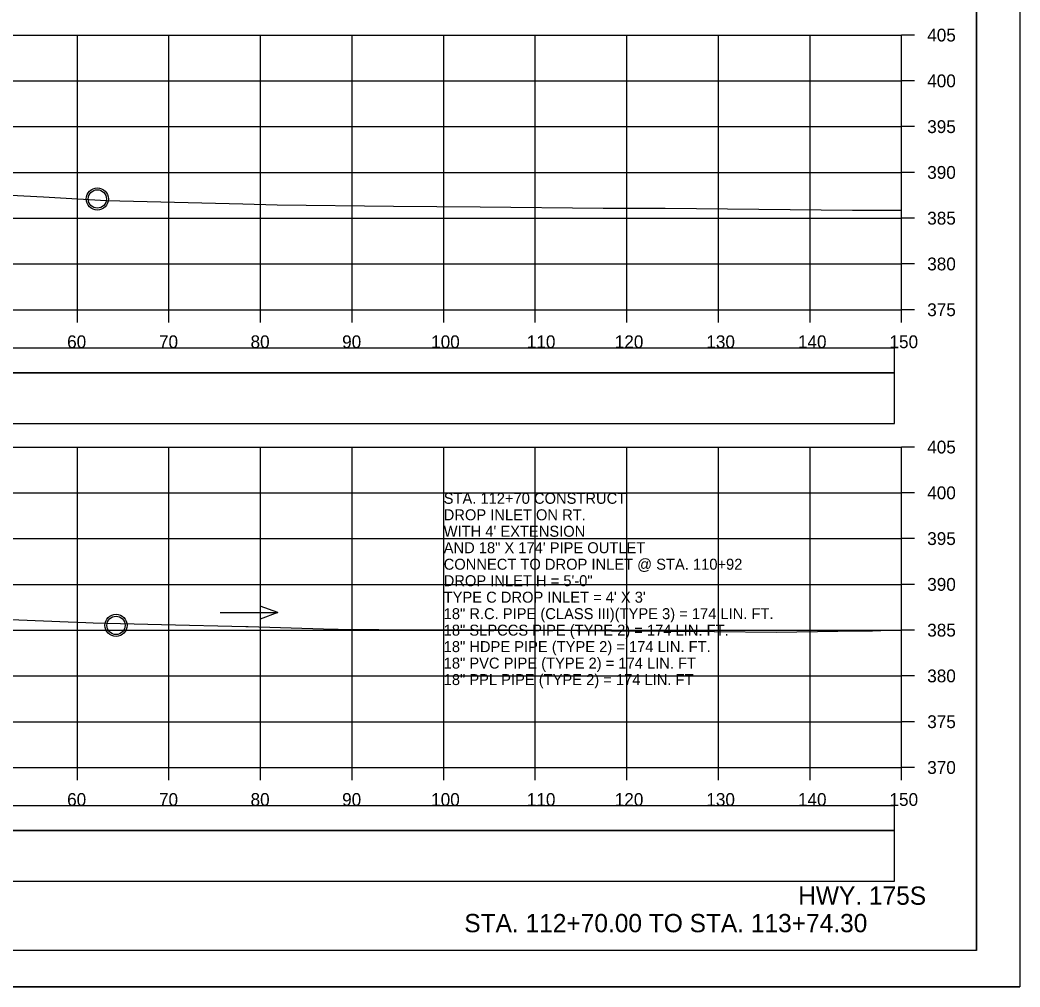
# Model space of a CAD drawing. Extents: x -37291014 to -37290680, y -936053 to -933067.
# Drawn here: x -37290789.4 to -37290680.2, y -933493.3 to -933387.6 of the extents above; entities that cross this region are included whole.
import ezdxf

# ---------------------------------------------------------------- set-up
doc = ezdxf.new("R2010")
doc.units = 0
for name, color, linetype in [('Default', 7, 'Continuous'), ('R_Axis', 7, 'Continuous'), ('R_Axis Annot', 7, 'Continuous'), ('R_Border', 7, 'Continuous'), ('R_Draft', 7, 'Continuous'), ('R_Exist Surface', 7, 'Continuous'), ('R_Grid', 7, 'Continuous'), ('R_No Plot', 7, 'Continuous'), ('R_Water', 7, 'Continuous'), ('R_Water Annot', 7, 'Continuous')]:
    doc.layers.add(name, color=color, linetype=linetype)

msp = doc.modelspace()

# ---------------------------------------------------------------- linework, layer by layer
at = {"layer": 'Default'}
for points in [[(-37290992.31, -933426.17), (-37290693.89, -933426.17), (-37290693.89, -933423.47), (-37290992.31, -933423.47)], [(-37290992.31, -933431.7), (-37290693.89, -933431.7), (-37290693.89, -933426.17), (-37290992.31, -933426.17)], [(-37290992.31, -933476.17), (-37290693.89, -933476.17), (-37290693.89, -933473.47), (-37290992.31, -933473.47)], [(-37290992.31, -933481.7), (-37290693.89, -933481.7), (-37290693.89, -933476.17), (-37290992.31, -933476.17)]]:
    msp.add_lwpolyline(points, close=True, dxfattribs=at)
at = {"layer": 'R_Axis'}
for p, q in [((-37290693.1, -933419.27), (-37290693.1, -933389.27)), ((-37290691.7, -933389.27), (-37290693.1, -933389.27)), ((-37290691.7, -933394.27), (-37290693.1, -933394.27)), ((-37290691.7, -933399.27), (-37290693.1, -933399.27)), ((-37290691.7, -933404.27), (-37290693.1, -933404.27)), ((-37290691.7, -933409.27), (-37290693.1, -933409.27)), ((-37290691.7, -933414.27), (-37290693.1, -933414.27)), ((-37290993.1, -933419.27), (-37290693.1, -933419.27)), ((-37290783.1, -933420.67), (-37290783.1, -933419.27)), ((-37290773.1, -933420.67), (-37290773.1, -933419.27)), ((-37290763.1, -933420.67), (-37290763.1, -933419.27)), ((-37290753.1, -933420.67), (-37290753.1, -933419.27)), ((-37290743.1, -933420.67), (-37290743.1, -933419.27)), ((-37290733.1, -933420.67), (-37290733.1, -933419.27)), ((-37290723.1, -933420.67), (-37290723.1, -933419.27)), ((-37290713.1, -933420.67), (-37290713.1, -933419.27)), ((-37290703.1, -933420.67), (-37290703.1, -933419.27)), ((-37290693.1, -933420.67), (-37290693.1, -933419.27)), ((-37290691.7, -933419.27), (-37290693.1, -933419.27)), ((-37290693.1, -933469.27), (-37290693.1, -933434.27)), ((-37290691.7, -933434.27), (-37290693.1, -933434.27)), ((-37290691.7, -933439.27), (-37290693.1, -933439.27)), ((-37290691.7, -933444.27), (-37290693.1, -933444.27)), ((-37290691.7, -933449.27), (-37290693.1, -933449.27)), ((-37290691.7, -933454.27), (-37290693.1, -933454.27)), ((-37290691.7, -933459.27), (-37290693.1, -933459.27)), ((-37290691.7, -933464.27), (-37290693.1, -933464.27)), ((-37290993.1, -933469.27), (-37290693.1, -933469.27)), ((-37290783.1, -933470.67), (-37290783.1, -933469.27)), ((-37290773.1, -933470.67), (-37290773.1, -933469.27)), ((-37290763.1, -933470.67), (-37290763.1, -933469.27)), ((-37290753.1, -933470.67), (-37290753.1, -933469.27)), ((-37290743.1, -933470.67), (-37290743.1, -933469.27)), ((-37290733.1, -933470.67), (-37290733.1, -933469.27)), ((-37290723.1, -933470.67), (-37290723.1, -933469.27)), ((-37290713.1, -933470.67), (-37290713.1, -933469.27)), ((-37290703.1, -933470.67), (-37290703.1, -933469.27)), ((-37290693.1, -933470.67), (-37290693.1, -933469.27)), ((-37290691.7, -933469.27), (-37290693.1, -933469.27))]:
    msp.add_line(p, q, dxfattribs=at)
at = {"layer": 'R_Border'}
for q in [(-37290684.92, -933283.81), (-37291001.1, -933489.27)]:
    msp.add_line((-37290684.92, -933489.27), q, dxfattribs=at)
at = {"layer": 'R_Exist Surface'}
for points in [[(-37290798.22, -933406.34), (-37290786.8, -933406.94), (-37290779.95, -933407.35), (-37290765.05, -933407.72), (-37290761.3, -933407.82), (-37290748.58, -933407.95), (-37290739.12, -933408.03), (-37290725.67, -933408.17), (-37290718.91, -933408.17), (-37290698.45, -933408.38), (-37290695.07, -933408.39), (-37290693.1, -933408.4)], [(-37290802.09, -933452.63), (-37290784.1, -933453.35), (-37290782.16, -933453.44), (-37290781.36, -933453.46), (-37290773.93, -933453.65), (-37290764.7, -933453.87), (-37290764.44, -933453.88), (-37290756.21, -933454.14), (-37290754.61, -933454.18), (-37290750.19, -933454.2), (-37290736.03, -933454.24), (-37290724.79, -933454.33), (-37290719.06, -933454.38), (-37290713.58, -933454.43), (-37290706.77, -933454.48), (-37290700.07, -933454.39), (-37290696.26, -933454.34), (-37290694.41, -933454.28), (-37290693.1, -933454.27)]]:
    msp.add_lwpolyline(points, dxfattribs=at)
at = {"layer": 'R_Grid'}
for p, q in [((-37290993.1, -933389.27), (-37290693.1, -933389.27)), ((-37290783.1, -933419.27), (-37290783.1, -933389.27)), ((-37290773.1, -933419.27), (-37290773.1, -933389.27)), ((-37290763.1, -933419.27), (-37290763.1, -933389.27)), ((-37290753.1, -933419.27), (-37290753.1, -933389.27)), ((-37290743.1, -933419.27), (-37290743.1, -933389.27)), ((-37290733.1, -933419.27), (-37290733.1, -933389.27)), ((-37290723.1, -933419.27), (-37290723.1, -933389.27)), ((-37290713.1, -933419.27), (-37290713.1, -933389.27)), ((-37290703.1, -933419.27), (-37290703.1, -933389.27)), ((-37290693.1, -933419.27), (-37290693.1, -933389.27)), ((-37290993.1, -933394.27), (-37290693.1, -933394.27)), ((-37290993.1, -933399.27), (-37290693.1, -933399.27)), ((-37290993.1, -933404.27), (-37290693.1, -933404.27)), ((-37290993.1, -933409.27), (-37290693.1, -933409.27)), ((-37290993.1, -933414.27), (-37290693.1, -933414.27)), ((-37290993.1, -933419.27), (-37290693.1, -933419.27)), ((-37290993.1, -933434.27), (-37290693.1, -933434.27)), ((-37290783.1, -933469.27), (-37290783.1, -933434.27)), ((-37290773.1, -933469.27), (-37290773.1, -933434.27)), ((-37290763.1, -933469.27), (-37290763.1, -933434.27)), ((-37290753.1, -933469.27), (-37290753.1, -933434.27)), ((-37290743.1, -933469.27), (-37290743.1, -933434.27)), ((-37290733.1, -933469.27), (-37290733.1, -933434.27)), ((-37290723.1, -933469.27), (-37290723.1, -933434.27)), ((-37290713.1, -933469.27), (-37290713.1, -933434.27)), ((-37290703.1, -933469.27), (-37290703.1, -933434.27)), ((-37290693.1, -933469.27), (-37290693.1, -933434.27)), ((-37290993.1, -933439.27), (-37290693.1, -933439.27)), ((-37290993.1, -933444.27), (-37290693.1, -933444.27)), ((-37290993.1, -933449.27), (-37290693.1, -933449.27)), ((-37290993.1, -933454.27), (-37290693.1, -933454.27)), ((-37290993.1, -933459.27), (-37290693.1, -933459.27)), ((-37290993.1, -933464.27), (-37290693.1, -933464.27)), ((-37290993.1, -933469.27), (-37290693.1, -933469.27))]:
    msp.add_line(p, q, dxfattribs=at)
at = {"layer": 'R_No Plot'}
msp.add_line((-37291013.5, -933493.25), (-37290680.17, -933493.25), dxfattribs=at)
for points in [[(-37291013.51, -933279.91), (-37290680.17, -933279.91), (-37290680.17, -933493.25), (-37291013.51, -933493.25)], [(-37290767.18, -933283.81), (-37290747.56, -933283.81), (-37290747.56, -933293.69), (-37290731.45, -933293.69), (-37290708.25, -933293.69), (-37290708.25, -933318.02), (-37290684.92, -933318.02), (-37290684.92, -933489.27), (-37291001.1, -933489.27), (-37291001.1, -933283.81)]]:
    msp.add_lwpolyline(points, close=True, dxfattribs=at)
for centre in [(-37290780.92, -933407.17), (-37290778.88, -933453.75)]:
    msp.add_circle(centre, 1.21, dxfattribs=at)
at = {"layer": 'R_Water'}
for centre in [(-37290780.92, -933407.17), (-37290778.88, -933453.75)]:
    msp.add_circle(centre, 1, dxfattribs=at)
at = {"layer": 'R_Water Annot'}
for p, q in [((-37290761.21, -933452.36), (-37290763.13, -933451.66)), ((-37290767.49, -933452.36), (-37290761.21, -933452.36)), ((-37290761.21, -933452.36), (-37290763.13, -933453.06))]:
    msp.add_line(p, q, dxfattribs=at)

# ---------------------------------------------------------------- texts
at = {"layer": 'R_Axis Annot'}
for s, p in [('405', (-37290690.3, -933389.97)), ('400', (-37290690.3, -933394.97)), ('395', (-37290690.3, -933399.97)), ('390', (-37290690.3, -933404.97)), ('385', (-37290690.3, -933409.97)), ('380', (-37290690.3, -933414.97)), ('375', (-37290690.3, -933419.97)), ('60', (-37290784.22, -933423.47)), ('70', (-37290774.19, -933423.47)), ('80', (-37290764.19, -933423.47)), ('90', (-37290754.19, -933423.47)), ('100', (-37290744.47, -933423.47)), ('110', (-37290734.02, -933423.47)), ('120', (-37290724.42, -933423.47)), ('130', (-37290714.42, -933423.47)), ('140', (-37290704.42, -933423.47)), ('150', (-37290694.42, -933423.47)), ('405', (-37290690.3, -933434.97)), ('400', (-37290690.3, -933439.97)), ('395', (-37290690.3, -933444.97)), ('390', (-37290690.3, -933449.97)), ('385', (-37290690.3, -933454.97)), ('380', (-37290690.3, -933459.97)), ('375', (-37290690.3, -933464.97)), ('370', (-37290690.3, -933469.97)), ('60', (-37290784.22, -933473.47)), ('70', (-37290774.19, -933473.47)), ('80', (-37290764.19, -933473.47)), ('90', (-37290754.19, -933473.47)), ('100', (-37290744.47, -933473.47)), ('110', (-37290734.02, -933473.47)), ('120', (-37290724.42, -933473.47)), ('130', (-37290714.42, -933473.47)), ('140', (-37290704.42, -933473.47)), ('150', (-37290694.42, -933473.47))]:
    msp.add_text(s, height=1.4, dxfattribs=at).set_placement(p)
at = {"layer": 'R_Draft'}
for s, p in [('HWY. 175S', (-37290704.39, -933484.27)), ('STA. 112+70.00 TO STA. 113+74.30', (-37290740.85, -933487.27))]:
    msp.add_text(s, height=2, dxfattribs=at).set_placement(p)
at = {"layer": 'R_Water Annot'}
for s, p in [('STA. 112+70 CONSTRUCT', (-37290743.1, -933440.47)), ('DROP INLET ON RT.', (-37290743.1, -933442.27)), ("WITH 4' EXTENSION", (-37290743.1, -933444.07)), ('AND 18" X 174\' PIPE OUTLET', (-37290743.1, -933445.87)), ('CONNECT TO DROP INLET @ STA. 110+92', (-37290743.1, -933447.67)), ('DROP INLET H = 5\'-0"', (-37290743.1, -933449.47)), ("TYPE C DROP INLET = 4' X 3'", (-37290743.1, -933451.27)), ('18" R.C. PIPE (CLASS III)(TYPE 3) = 174 LIN. FT.', (-37290743.1, -933453.07)), ('18" SLPCCS PIPE (TYPE 2) = 174 LIN. FT.', (-37290743.1, -933454.87)), ('18" HDPE PIPE (TYPE 2) = 174 LIN. FT.', (-37290743.1, -933456.67)), ('18" PVC PIPE (TYPE 2) = 174 LIN. FT', (-37290743.1, -933458.47)), ('18" PPL PIPE (TYPE 2) = 174 LIN. FT', (-37290743.1, -933460.27))]:
    msp.add_text(s, height=1.2, dxfattribs=at).set_placement(p)

doc.saveas('drawing.dxf')
